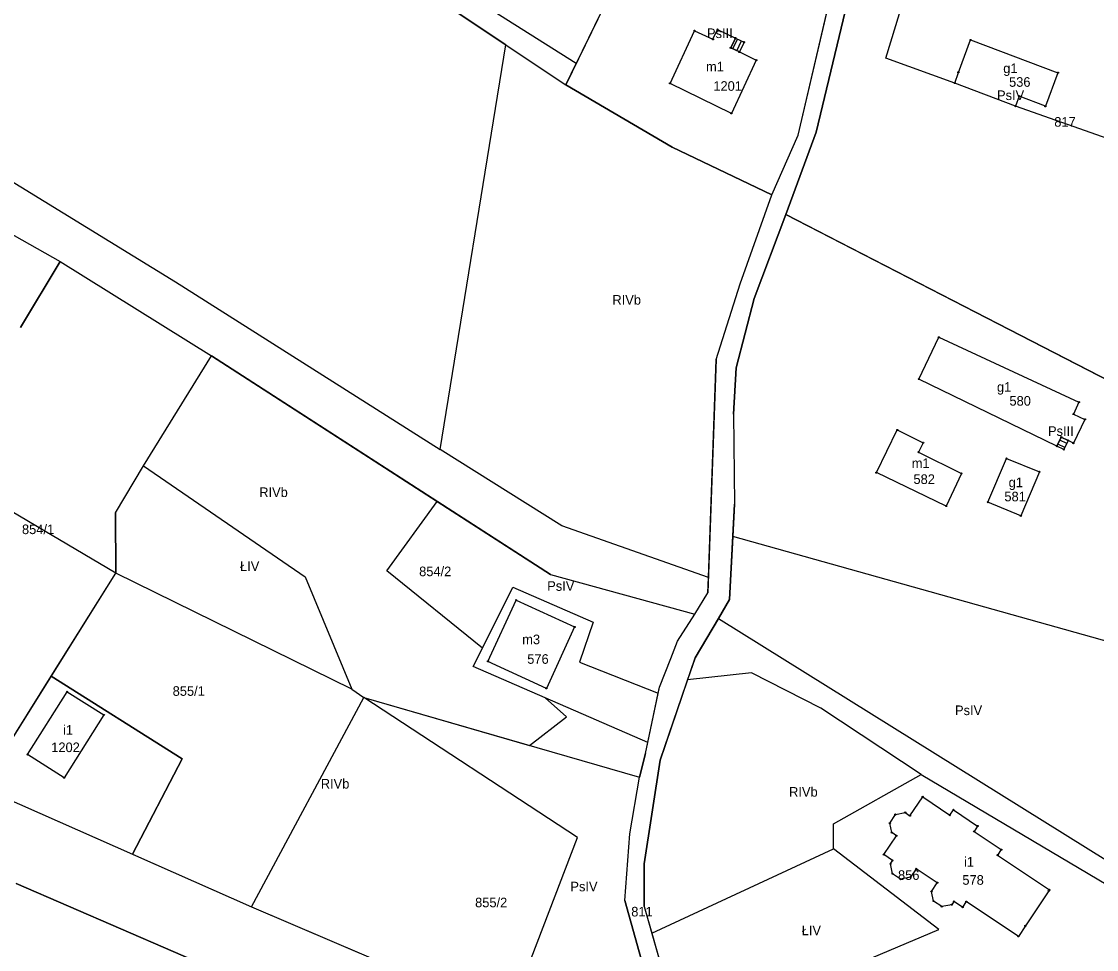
# Model space of a CAD drawing. Extents: x 7498273 to 7499989, y 5499795 to 5500810.
# Drawn here: x 7499733.8 to 7499901.7, y 5500078.2 to 5500223.1 of the extents above; entities that cross this region are included whole.
import ezdxf

# ---------------------------------------------------------------- set-up
doc = ezdxf.new("R2010")
doc.units = 0
for name, color, linetype in [('209-oznaczenie konturu klasyfikacyjnego', 7, 'Continuous'), ('211-numer działki ewidencyjnej', 7, 'Continuous'), ('217-kontur klasyfikacyjny', 7, 'Continuous'), ('218-kontur użytku gruntowego', 7, 'Continuous'), ('219-działka ewidencyjna', 7, 'Continuous'), ('312-budynek ewidencyjny', 7, 'Continuous'), ('312-oznaczenie budynku ewidencyjnego', 7, 'Continuous'), ('312-oznaczenie budynku ewidencyjnego-Atr117', 7, 'Continuous'), ('352-schody', 7, 'Continuous'), ('Punkt budynku', 7, 'Continuous')]:
    doc.layers.add(name, color=color, linetype=linetype)

# ---------------------------------------------------------------- blocks, each defined once
blk = doc.blocks.new('PUNKTBUD')
blk.add_circle((0, 0), 0.09)

msp = doc.modelspace()

# ---------------------------------------------------------------- linework, layer by layer
at = {"layer": '217-kontur klasyfikacyjny'}
for points in [[(7499820.43, 5500216.51), (7499761.94, 5500253.41)], [(7499830.99, 5500238.25), (7499820.43, 5500216.51)], [(7499868.76, 5500217.34), (7499875.38, 5500238.98)], [(7499809.45, 5500219.44), (7499793.24, 5500230.24)], [(7499855.09, 5500205.31), (7499859.81, 5500225.64)], [(7499862.79, 5500226.15), (7499857.88, 5500205.77)], [(7499799.17, 5500156.23), (7499809.45, 5500219.44)], [(7499809.45, 5500219.44), (7499818.82, 5500213.2)], [(7499818.82, 5500213.2), (7499820.43, 5500216.51)], [(7499879.54, 5500213.47), (7499868.76, 5500217.34)], [(7499835.4, 5500203.45), (7499818.82, 5500213.2)], [(7499889, 5500209.85), (7499879.54, 5500213.47)], [(7499693.1, 5500212), (7499739.84, 5500185.6)], [(7499709.49, 5500212.1), (7499757.83, 5500182.41)], [(7499917.09, 5500199.97), (7499889, 5500209.85)], [(7499850.96, 5500196.01), (7499855.09, 5500205.31)], [(7499857.88, 5500205.77), (7499853.17, 5500192.92)], [(7499850.96, 5500196.01), (7499835.4, 5500203.45)], [(7499846.04, 5500182.11), (7499850.96, 5500196.01)], [(7499853.17, 5500192.92), (7499848.2, 5500179.81)], [(7499859.7, 5500189.56), (7499853.17, 5500192.92)], [(7499911.06, 5500163.14), (7499859.7, 5500189.56)], [(7499739.84, 5500185.6), (7499733.63, 5500175.28)], [(7499739.84, 5500185.6), (7499763.47, 5500170.85)], [(7499757.83, 5500182.41), (7499799.17, 5500156.23)], [(7499842.25, 5500170.29), (7499846.04, 5500182.11)], [(7499848.2, 5500179.81), (7499845.39, 5500168.97)], [(7499763.47, 5500170.85), (7499798.71, 5500148.14)], [(7499841.06, 5500136.28), (7499842.25, 5500170.29)], [(7499845.39, 5500168.97), (7499844.99, 5500161.76)], [(7499844.99, 5500161.76), (7499845.13, 5500147.73)], [(7499818.19, 5500144.35), (7499799.17, 5500156.23)], [(7499748.5, 5500136.91), (7499720.92, 5500153.25)], [(7499748.46, 5500146.34), (7499752.86, 5500153.7)], [(7499752.86, 5500153.7), (7499778.07, 5500136.38)], [(7499790.86, 5500137.29), (7499798.71, 5500148.14)], [(7499798.71, 5500148.14), (7499816.4, 5500136.74)], [(7499845.13, 5500147.73), (7499844.87, 5500142.67)], [(7499748.5, 5500136.91), (7499748.46, 5500146.34)], [(7499841.06, 5500136.28), (7499818.19, 5500144.35)], [(7499844.87, 5500142.67), (7499844.37, 5500132.83)], [(7499919.32, 5500121.81), (7499844.87, 5500142.67)], [(7499738.44, 5500120.85), (7499748.5, 5500136.91)], [(7499785.38, 5500118.84), (7499748.5, 5500136.91)], [(7499778.07, 5500136.38), (7499785.38, 5500118.84)], [(7499805.77, 5500125.2), (7499790.86, 5500137.29)], [(7499816.4, 5500136.74), (7499838.92, 5500130.55)], [(7499840.98, 5500133.86), (7499841.06, 5500136.28)], [(7499805.77, 5500125.2), (7499810.51, 5500134.73)], [(7499810.51, 5500134.73), (7499823.06, 5500129.28)], [(7499838.92, 5500130.55), (7499840.98, 5500133.86)], [(7499844.37, 5500132.83), (7499842.63, 5500129.86)], [(7499823.06, 5500129.28), (7499820.94, 5500123.03)], [(7499836.25, 5500126.3), (7499838.92, 5500130.55)], [(7499842.63, 5500129.86), (7499838.99, 5500123.73)], [(7499835.18, 5500123.59), (7499836.25, 5500126.3)], [(7499804.33, 5500122.34), (7499805.77, 5500125.2)], [(7499820.94, 5500123.03), (7499833.23, 5500118.22)], [(7499833.42, 5500119.13), (7499835.18, 5500123.59)], [(7499838.99, 5500123.73), (7499837.81, 5500120.29)], [(7499727.54, 5500103.45), (7499738.44, 5500120.85)], [(7499738.44, 5500120.85), (7499758.86, 5500107.92)], [(7499815.57, 5500117.46), (7499804.33, 5500122.34)], [(7499847.79, 5500121.35), (7499837.81, 5500120.29)], [(7499858.64, 5500115.83), (7499847.79, 5500121.35)], [(7499833.23, 5500118.22), (7499833.42, 5500119.13)], [(7499837.81, 5500120.29), (7499833.51, 5500107.72)], [(7499785.38, 5500118.84), (7499787.26, 5500117.51)], [(7499787.26, 5500117.51), (7499813.11, 5500110.04)], [(7499820.62, 5500095.66), (7499787.26, 5500117.51)], [(7499818.92, 5500114.48), (7499815.57, 5500117.46)], [(7499831.59, 5500110.5), (7499815.57, 5500117.46)], [(7499874.29, 5500105.47), (7499858.64, 5500115.83)], [(7499813.11, 5500110.04), (7499818.92, 5500114.48)], [(7499831.23, 5500108.78), (7499831.59, 5500110.5)], [(7499758.86, 5500107.92), (7499751.15, 5500093.04)], [(7499830.28, 5500105.07), (7499831.23, 5500108.78)], [(7499833.51, 5500107.72), (7499831.02, 5500091.56)], [(7499828.78, 5500096.23), (7499830.28, 5500105.07)], [(7499860.59, 5500097.79), (7499874.29, 5500105.47)], [(7499874.29, 5500105.47), (7499909.06, 5500084.87)], [(7499860.59, 5500093.87), (7499860.59, 5500097.79)], [(7499809.87, 5500067.68), (7499820.62, 5500095.66)], [(7499828.01, 5500085.83), (7499828.78, 5500096.23)], [(7499832.23, 5500080.7), (7499860.59, 5500093.87)], [(7499877.02, 5500081.3), (7499860.59, 5500093.87)], [(7499751.15, 5500093.04), (7499769.73, 5500084.85)], [(7499831.02, 5500091.56), (7499831.05, 5500084.88)], [(7499773.8, 5500070.79), (7499732.95, 5500088.45)], [(7499831.84, 5500072.04), (7499828.01, 5500085.83)], [(7499769.73, 5500084.85), (7499809.87, 5500067.68)], [(7499831.05, 5500084.88), (7499832.23, 5500080.7)], [(7499832.23, 5500080.7), (7499834.86, 5500071.33)], [(7499838.24, 5500064.92), (7499877.02, 5500081.3)]]:
    msp.add_lwpolyline(points, dxfattribs=at)
at = {"layer": '218-kontur użytku gruntowego'}
for points in [[(7499820.43, 5500216.51), (7499761.94, 5500253.41)], [(7499830.99, 5500238.25), (7499820.43, 5500216.51)], [(7499868.76, 5500217.34), (7499875.38, 5500238.98)], [(7499809.45, 5500219.44), (7499793.24, 5500230.24)], [(7499855.09, 5500205.31), (7499859.81, 5500225.64)], [(7499862.79, 5500226.15), (7499857.88, 5500205.77)], [(7499799.17, 5500156.23), (7499809.45, 5500219.44)], [(7499809.45, 5500219.44), (7499818.82, 5500213.2)], [(7499818.82, 5500213.2), (7499820.43, 5500216.51)], [(7499879.54, 5500213.47), (7499868.76, 5500217.34)], [(7499835.4, 5500203.45), (7499818.82, 5500213.2)], [(7499889, 5500209.85), (7499879.54, 5500213.47)], [(7499693.1, 5500212), (7499739.84, 5500185.6)], [(7499709.49, 5500212.1), (7499757.83, 5500182.41)], [(7499917.09, 5500199.97), (7499889, 5500209.85)], [(7499850.96, 5500196.01), (7499855.09, 5500205.31)], [(7499857.88, 5500205.77), (7499853.17, 5500192.92)], [(7499850.96, 5500196.01), (7499835.4, 5500203.45)], [(7499846.04, 5500182.11), (7499850.96, 5500196.01)], [(7499853.17, 5500192.92), (7499848.2, 5500179.81)], [(7499859.7, 5500189.56), (7499853.17, 5500192.92)], [(7499911.06, 5500163.14), (7499859.7, 5500189.56)], [(7499739.84, 5500185.6), (7499733.63, 5500175.28)], [(7499739.84, 5500185.6), (7499763.47, 5500170.85)], [(7499757.83, 5500182.41), (7499799.17, 5500156.23)], [(7499842.25, 5500170.29), (7499846.04, 5500182.11)], [(7499848.2, 5500179.81), (7499845.39, 5500168.97)], [(7499763.47, 5500170.85), (7499798.71, 5500148.14)], [(7499841.06, 5500136.28), (7499842.25, 5500170.29)], [(7499845.39, 5500168.97), (7499844.99, 5500161.76)], [(7499844.99, 5500161.76), (7499845.13, 5500147.73)], [(7499818.19, 5500144.35), (7499799.17, 5500156.23)], [(7499748.5, 5500136.91), (7499720.92, 5500153.25)], [(7499748.46, 5500146.34), (7499752.86, 5500153.7)], [(7499752.86, 5500153.7), (7499778.07, 5500136.38)], [(7499790.86, 5500137.29), (7499798.71, 5500148.14)], [(7499798.71, 5500148.14), (7499816.4, 5500136.74)], [(7499845.13, 5500147.73), (7499844.87, 5500142.67)], [(7499748.5, 5500136.91), (7499748.46, 5500146.34)], [(7499841.06, 5500136.28), (7499818.19, 5500144.35)], [(7499844.87, 5500142.67), (7499844.37, 5500132.83)], [(7499919.32, 5500121.81), (7499844.87, 5500142.67)], [(7499738.44, 5500120.85), (7499748.5, 5500136.91)], [(7499785.38, 5500118.84), (7499748.5, 5500136.91)], [(7499778.07, 5500136.38), (7499785.38, 5500118.84)], [(7499805.77, 5500125.2), (7499790.86, 5500137.29)], [(7499816.4, 5500136.74), (7499838.92, 5500130.55)], [(7499840.98, 5500133.86), (7499841.06, 5500136.28)], [(7499805.77, 5500125.2), (7499810.51, 5500134.73)], [(7499810.51, 5500134.73), (7499823.06, 5500129.28)], [(7499838.92, 5500130.55), (7499840.98, 5500133.86)], [(7499844.37, 5500132.83), (7499842.63, 5500129.86)], [(7499823.06, 5500129.28), (7499820.94, 5500123.03)], [(7499836.25, 5500126.3), (7499838.92, 5500130.55)], [(7499842.63, 5500129.86), (7499838.99, 5500123.73)], [(7499835.18, 5500123.59), (7499836.25, 5500126.3)], [(7499804.33, 5500122.34), (7499805.77, 5500125.2)], [(7499820.94, 5500123.03), (7499833.23, 5500118.22)], [(7499833.42, 5500119.13), (7499835.18, 5500123.59)], [(7499838.99, 5500123.73), (7499837.81, 5500120.29)], [(7499727.54, 5500103.45), (7499738.44, 5500120.85)], [(7499758.86, 5500107.92), (7499738.44, 5500120.85)], [(7499815.57, 5500117.46), (7499804.33, 5500122.34)], [(7499847.79, 5500121.35), (7499837.81, 5500120.29)], [(7499858.64, 5500115.83), (7499847.79, 5500121.35)], [(7499833.23, 5500118.22), (7499833.42, 5500119.13)], [(7499837.81, 5500120.29), (7499833.51, 5500107.72)], [(7499785.38, 5500118.84), (7499787.26, 5500117.51)], [(7499787.26, 5500117.51), (7499813.11, 5500110.04)], [(7499820.62, 5500095.66), (7499787.26, 5500117.51)], [(7499818.92, 5500114.48), (7499815.57, 5500117.46)], [(7499831.59, 5500110.5), (7499815.57, 5500117.46)], [(7499831.59, 5500110.5), (7499833.23, 5500118.22)], [(7499874.29, 5500105.47), (7499858.64, 5500115.83)], [(7499813.11, 5500110.04), (7499818.92, 5500114.48)], [(7499831.23, 5500108.78), (7499831.59, 5500110.5)], [(7499751.15, 5500093.04), (7499758.86, 5500107.92)], [(7499830.28, 5500105.07), (7499831.23, 5500108.78)], [(7499833.51, 5500107.72), (7499831.02, 5500091.56)], [(7499828.78, 5500096.23), (7499830.28, 5500105.07)], [(7499860.59, 5500097.79), (7499874.29, 5500105.47)], [(7499874.29, 5500105.47), (7499909.06, 5500084.87)], [(7499727.54, 5500103.45), (7499751.15, 5500093.04)], [(7499860.59, 5500093.87), (7499860.59, 5500097.79)], [(7499809.87, 5500067.68), (7499820.62, 5500095.66)], [(7499828.01, 5500085.83), (7499828.78, 5500096.23)], [(7499832.23, 5500080.7), (7499860.59, 5500093.87)], [(7499877.02, 5500081.3), (7499860.59, 5500093.87)], [(7499751.15, 5500093.04), (7499769.73, 5500084.85)], [(7499831.02, 5500091.56), (7499831.05, 5500084.88)], [(7499773.8, 5500070.79), (7499732.95, 5500088.45)], [(7499831.84, 5500072.04), (7499828.01, 5500085.83)], [(7499769.73, 5500084.85), (7499809.87, 5500067.68)], [(7499831.05, 5500084.88), (7499832.23, 5500080.7)], [(7499832.23, 5500080.7), (7499834.86, 5500071.33)], [(7499838.24, 5500064.92), (7499877.02, 5500081.3)]]:
    msp.add_lwpolyline(points, dxfattribs=at)
at = {"layer": '219-działka ewidencyjna'}
for points in [[(7499834.82, 5500246.12), (7499818.82, 5500213.2)], [(7499793.24, 5500230.24), (7499818.82, 5500213.2)], [(7499855.09, 5500205.31), (7499860.31, 5500227.8)], [(7499857.88, 5500205.77), (7499862.79, 5500226.15)], [(7499818.82, 5500213.2), (7499835.4, 5500203.45)], [(7499693.1, 5500212), (7499739.84, 5500185.6)], [(7499850.96, 5500196.01), (7499855.09, 5500205.31)], [(7499853.17, 5500192.92), (7499857.88, 5500205.77)], [(7499835.4, 5500203.45), (7499850.96, 5500196.01)], [(7499846.04, 5500182.11), (7499850.96, 5500196.01)], [(7499848.2, 5500179.81), (7499853.17, 5500192.92)], [(7499853.17, 5500192.92), (7499915.93, 5500160.63)], [(7499733.63, 5500175.28), (7499739.84, 5500185.6)], [(7499739.84, 5500185.6), (7499763.47, 5500170.85)], [(7499842.25, 5500170.29), (7499846.04, 5500182.11)], [(7499845.39, 5500168.97), (7499848.2, 5500179.81)], [(7499752.86, 5500153.7), (7499763.47, 5500170.85)], [(7499816.4, 5500136.74), (7499763.47, 5500170.85)], [(7499842.25, 5500170.29), (7499840.98, 5500133.86)], [(7499844.99, 5500161.76), (7499845.39, 5500168.97)], [(7499844.99, 5500161.76), (7499845.13, 5500147.73)], [(7499748.46, 5500146.34), (7499752.86, 5500153.7)], [(7499752.86, 5500153.7), (7499778.07, 5500136.38)], [(7499844.37, 5500132.83), (7499845.13, 5500147.73)], [(7499748.46, 5500146.34), (7499748.5, 5500136.91)], [(7499727.54, 5500103.45), (7499748.5, 5500136.91)], [(7499778.07, 5500136.38), (7499785.38, 5500118.84)], [(7499816.4, 5500136.74), (7499838.92, 5500130.55)], [(7499838.92, 5500130.55), (7499840.98, 5500133.86)], [(7499842.63, 5500129.86), (7499844.37, 5500132.83)], [(7499836.25, 5500126.3), (7499838.92, 5500130.55)], [(7499838.99, 5500123.73), (7499842.63, 5500129.86)], [(7499842.63, 5500129.86), (7499910.31, 5500087.68)], [(7499835.18, 5500123.59), (7499836.25, 5500126.3)], [(7499833.42, 5500119.13), (7499835.18, 5500123.59)], [(7499833.51, 5500107.72), (7499838.99, 5500123.73)], [(7499831.23, 5500108.78), (7499833.42, 5500119.13)], [(7499769.73, 5500084.85), (7499787.26, 5500117.51)], [(7499785.38, 5500118.84), (7499787.26, 5500117.51)], [(7499787.26, 5500117.51), (7499830.28, 5500105.07)], [(7499831.23, 5500108.78), (7499830.28, 5500105.07)], [(7499831.02, 5500091.56), (7499833.51, 5500107.72)], [(7499828.78, 5500096.23), (7499830.28, 5500105.07)], [(7499727.54, 5500103.45), (7499769.73, 5500084.85)], [(7499828.01, 5500085.83), (7499828.78, 5500096.23)], [(7499831.05, 5500084.88), (7499831.02, 5500091.56)], [(7499732.95, 5500088.45), (7499773.8, 5500070.79)], [(7499828.01, 5500085.83), (7499831.84, 5500072.04)], [(7499769.73, 5500084.85), (7499839.53, 5500055)], [(7499831.05, 5500084.88), (7499834.86, 5500071.33)]]:
    msp.add_lwpolyline(points, dxfattribs=at)
at = {"layer": '312-budynek ewidencyjny'}
for points in [[(7499835.07, 5500213.42), (7499838.89, 5500221.64)], [(7499838.89, 5500221.64), (7499841.77, 5500220.3)], [(7499841.77, 5500220.3), (7499842.48, 5500221.83)], [(7499842.48, 5500221.83), (7499845.27, 5500220.49)], [(7499845.27, 5500220.49), (7499844.54, 5500218.97)], [(7499880.09, 5500215.13), (7499881.99, 5500220.2)], [(7499881.99, 5500220.2), (7499895.65, 5500215.08)], [(7499844.54, 5500218.97), (7499845.89, 5500218.32)], [(7499845.89, 5500218.32), (7499848.54, 5500217.04)], [(7499848.54, 5500217.04), (7499844.65, 5500208.73)], [(7499879.54, 5500213.47), (7499880.09, 5500215.13)], [(7499895.65, 5500215.08), (7499893.68, 5500209.84)], [(7499844.65, 5500208.73), (7499835.07, 5500213.42)], [(7499889, 5500209.85), (7499879.54, 5500213.47)], [(7499889.61, 5500211.43), (7499889, 5500209.85)], [(7499893.68, 5500209.84), (7499889.61, 5500211.43)], [(7499873.91, 5500167.24), (7499877.05, 5500173.76)], [(7499877.05, 5500173.76), (7499898.92, 5500163.63)], [(7499895.48, 5500156.75), (7499873.91, 5500167.24)], [(7499898.92, 5500163.63), (7499898.07, 5500161.78)], [(7499898.07, 5500161.78), (7499899.86, 5500160.95)], [(7499867.29, 5500152.63), (7499870.55, 5500159.3)], [(7499870.55, 5500159.3), (7499874.6, 5500157.3)], [(7499899.86, 5500160.95), (7499898.05, 5500157.24)], [(7499896.16, 5500158.16), (7499895.48, 5500156.75)], [(7499897.24, 5500157.64), (7499896.16, 5500158.16)], [(7499898.05, 5500157.24), (7499897.24, 5500157.64)], [(7499874.6, 5500157.3), (7499873.87, 5500155.83)], [(7499873.87, 5500155.83), (7499880.59, 5500152.5)], [(7499884.69, 5500148.02), (7499887.61, 5500154.84)], [(7499887.61, 5500154.84), (7499892.75, 5500152.76)], [(7499878.2, 5500147.41), (7499867.29, 5500152.63)], [(7499892.75, 5500152.76), (7499889.84, 5500145.87)], [(7499880.59, 5500152.5), (7499878.2, 5500147.41)], [(7499889.84, 5500145.87), (7499884.69, 5500148.02)], [(7499806.63, 5500123.16), (7499811.04, 5500132.73)], [(7499811.04, 5500132.73), (7499820.17, 5500128.53)], [(7499820.17, 5500128.53), (7499815.76, 5500118.95)], [(7499815.76, 5500118.95), (7499806.63, 5500123.16)], [(7499734.73, 5500108.62), (7499740.93, 5500118.41)], [(7499740.93, 5500118.41), (7499746.65, 5500114.79)], [(7499746.65, 5500114.79), (7499740.45, 5500105)], [(7499740.45, 5500105), (7499734.73, 5500108.62)], [(7499872.53, 5500099.06), (7499874.52, 5500102.02)], [(7499874.52, 5500102.02), (7499878.77, 5500099.14)], [(7499869.38, 5500097.92), (7499870.25, 5500099.26)], [(7499870.25, 5500099.26), (7499871.8, 5500099.56)], [(7499871.8, 5500099.56), (7499872.53, 5500099.06)], [(7499878.77, 5500099.14), (7499879.33, 5500099.97)], [(7499879.33, 5500099.97), (7499883.1, 5500097.45)], [(7499869.71, 5500096.42), (7499869.38, 5500097.92)], [(7499883.1, 5500097.45), (7499882.55, 5500096.62)], [(7499868.46, 5500092.98), (7499870.43, 5500095.94)], [(7499870.43, 5500095.94), (7499869.71, 5500096.42)], [(7499882.55, 5500096.62), (7499886.8, 5500093.77)], [(7499869.82, 5500092.06), (7499868.46, 5500092.98)], [(7499886.8, 5500093.77), (7499886.22, 5500092.9)], [(7499886.22, 5500092.9), (7499894.32, 5500087.49)], [(7499869.48, 5500091.55), (7499869.82, 5500092.06)], [(7499869.82, 5500090.01), (7499869.48, 5500091.55)], [(7499873.49, 5500090.78), (7499872.62, 5500089.47)], [(7499876.8, 5500088.6), (7499873.49, 5500090.78)], [(7499871.08, 5500089.16), (7499869.82, 5500090.01)], [(7499872.62, 5500089.47), (7499871.08, 5500089.16)], [(7499875.9, 5500087.25), (7499876.8, 5500088.6)], [(7499876.21, 5500085.73), (7499875.9, 5500087.25)], [(7499894.22, 5500087.35), (7499890.56, 5500081.86)], [(7499894.32, 5500087.49), (7499894.22, 5500087.35)], [(7499877.49, 5500084.87), (7499876.21, 5500085.73)], [(7499879.38, 5500085.67), (7499879.05, 5500085.17)], [(7499880.76, 5500084.78), (7499879.38, 5500085.67)], [(7499881.33, 5500085.64), (7499880.76, 5500084.78)], [(7499889.47, 5500080.22), (7499881.33, 5500085.64)], [(7499879.05, 5500085.17), (7499877.49, 5500084.87)], [(7499890.56, 5500081.86), (7499889.47, 5500080.22)]]:
    msp.add_lwpolyline(points, dxfattribs=at)
at = {"layer": '352-schody'}
for points in [[(7499845.27, 5500220.49), (7499846.62, 5500219.84), (7499845.89, 5500218.32), (7499844.54, 5500218.97)], [(7499845.27, 5500220.49), (7499846.62, 5500219.84), (7499845.89, 5500218.32), (7499844.54, 5500218.97)], [(7499895.48, 5500156.75), (7499896.16, 5500158.16), (7499897.24, 5500157.64), (7499896.56, 5500156.23)], [(7499895.48, 5500156.75), (7499896.16, 5500158.16), (7499897.24, 5500157.64), (7499896.56, 5500156.23)]]:
    msp.add_lwpolyline(points, close=True, dxfattribs=at)
for points in [[(7499844.854, 5500218.819), (7499845.585, 5500220.338)], [(7499845.485, 5500218.515), (7499846.216, 5500220.034)], [(7499897.016, 5500157.175), (7499895.936, 5500157.696)], [(7499896.712, 5500156.545), (7499895.632, 5500157.065)]]:
    msp.add_lwpolyline(points, dxfattribs=at)

# ---------------------------------------------------------------- block references
at = {"layer": 'Punkt budynku'}
for p in [(7499838.89, 5500221.64), (7499842.48, 5500221.83), (7499841.77, 5500220.3), (7499845.27, 5500220.49), (7499846.62, 5500219.84), (7499881.99, 5500220.2), (7499844.54, 5500218.97), (7499845.89, 5500218.32), (7499848.54, 5500217.04), (7499880.09, 5500215.13), (7499895.65, 5500215.08), (7499835.07, 5500213.42), (7499879.54, 5500213.47), (7499889.61, 5500211.43), (7499889, 5500209.85), (7499893.68, 5500209.84), (7499844.65, 5500208.73), (7499877.05, 5500173.76), (7499873.91, 5500167.24), (7499898.92, 5500163.63), (7499898.07, 5500161.78), (7499899.86, 5500160.95), (7499870.55, 5500159.3), (7499896.16, 5500158.16), (7499897.24, 5500157.64), (7499874.6, 5500157.3), (7499895.48, 5500156.75), (7499896.56, 5500156.23), (7499898.05, 5500157.24), (7499873.87, 5500155.83), (7499887.61, 5500154.84), (7499867.29, 5500152.63), (7499880.59, 5500152.5), (7499892.75, 5500152.76), (7499884.69, 5500148.02), (7499878.2, 5500147.41), (7499889.84, 5500145.87), (7499811.04, 5500132.73), (7499820.17, 5500128.53), (7499806.63, 5500123.16), (7499815.76, 5500118.95), (7499740.93, 5500118.41), (7499746.65, 5500114.79), (7499734.73, 5500108.62), (7499740.45, 5500105), (7499874.52, 5500102.02), (7499870.25, 5500099.26), (7499871.8, 5500099.56), (7499872.53, 5500099.06), (7499878.77, 5500099.14), (7499879.33, 5500099.97), (7499869.38, 5500097.92), (7499883.1, 5500097.45), (7499869.71, 5500096.42), (7499870.43, 5500095.94), (7499882.55, 5500096.62), (7499886.8, 5500093.77), (7499868.46, 5500092.98), (7499869.82, 5500092.06), (7499886.22, 5500092.9), (7499869.48, 5500091.55), (7499873.49, 5500090.78), (7499869.82, 5500090.01), (7499871.08, 5500089.16), (7499872.62, 5500089.47), (7499875.9, 5500087.25), (7499876.8, 5500088.6), (7499894.22, 5500087.35), (7499894.32, 5500087.49), (7499876.21, 5500085.73), (7499879.38, 5500085.67), (7499881.33, 5500085.64), (7499877.49, 5500084.87), (7499879.05, 5500085.17), (7499880.76, 5500084.78), (7499890.56, 5500081.86), (7499889.47, 5500080.22)]:
    msp.add_blockref('PUNKTBUD', p, dxfattribs=at)

# ---------------------------------------------------------------- texts
at = {"layer": '209-oznaczenie konturu klasyfikacyjnego'}
for s, p in [('PsIII', (7499840.84, 5500220.49)), ('PsIV', (7499886.13, 5500210.81)), ('RIVb', (7499826.07, 5500178.86)), ('PsIII', (7499894.09, 5500158.37)), ('RIVb', (7499770.92, 5500148.82)), ('ŁIV', (7499767.92, 5500137.27)), ('PsIV', (7499815.89, 5500134.18)), ('PsIV', (7499879.57, 5500114.77)), ('RIVb', (7499780.53, 5500103.3)), ('RIVb', (7499853.66, 5500102.03)), ('PsIV', (7499819.51, 5500087.25)), ('ŁIV', (7499855.63, 5500080.4))]:
    msp.add_text(s, height=1.5, dxfattribs=at).set_placement(p)
at = {"layer": '211-numer działki ewidencyjnej'}
for s, p in [('817', (7499895.07, 5500206.65)), ('854/1', (7499733.87, 5500143.03)), ('854/2', (7499795.89, 5500136.46)), ('855/1', (7499757.4, 5500117.78)), ('856', (7499870.67, 5500089.04)), ('855/2', (7499804.63, 5500084.76)), ('811', (7499829.01, 5500083.33))]:
    msp.add_text(s, height=1.5, dxfattribs=at).set_placement(p)
at = {"layer": '312-oznaczenie budynku ewidencyjnego'}
for s, p in [('1201', (7499841.83, 5500212.25)), ('536', (7499888.01, 5500212.88)), ('580', (7499888.07, 5500163.09)), ('582', (7499873.08, 5500150.86)), ('581', (7499887.28, 5500148.15)), ('576', (7499812.77, 5500122.78)), ('1202', (7499738.44, 5500108.99)), ('578', (7499880.72, 5500088.28))]:
    msp.add_text(s, height=1.5, dxfattribs=at).set_placement(p)
at = {"layer": '312-oznaczenie budynku ewidencyjnego-Atr117'}
for s, p in [('m1', (7499840.685, 5500215.28)), ('g1', (7499887.099, 5500215.02)), ('g1', (7499886.119, 5500165.26)), ('m1', (7499872.815, 5500153.36)), ('g1', (7499887.949, 5500150.36)), ('m3', (7499811.986, 5500125.84)), ('i1', (7499740.272, 5500111.71)), ('i1', (7499880.972, 5500091.12))]:
    msp.add_text(s, height=1.5, dxfattribs=at).set_placement(p)

doc.saveas('drawing.dxf')
